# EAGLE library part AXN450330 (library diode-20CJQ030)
Matsushita P8 NARROW-PITCH CONNECTORS FOR PC BOARDS 50Pin Header NARROW-PITCH (0.8mm) CONNECTORS P8 SERIES FEATURES The product lineup consists of the low profile of: - 3 mm - 3.5 mm - 4 mm - 4.5 mm - 5 mm - 5.5 mm - 6 mm - 7 mm - 8 mm - 11.5 mm - 13 mm - 14 mm APPLICATIONS Small portable equipment, laptop computers, video equipment, radio communication, cellular telephones, etc. Please send any comments to: messi@users.sourceforge.net
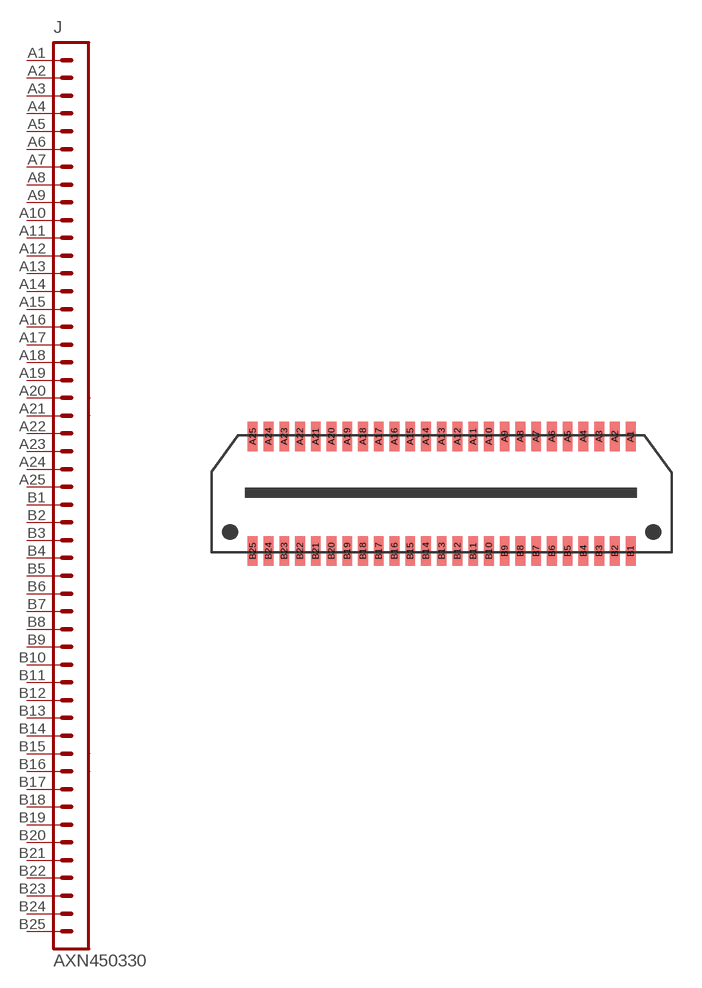
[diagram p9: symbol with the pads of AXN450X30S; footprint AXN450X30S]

Designator prefix J

## AXN450330  [AXN450X30S]
A1  1  pas
A2  2  pas
A3  3  pas
A4  4  pas
A5  5  pas
A6  6  pas
A7  7  pas
A8  8  pas
A9  9  pas
A10  10  pas
A11  11  pas
A12  12  pas
A13  13  pas
A14  14  pas
A15  15  pas
A16  16  pas
A17  17  pas
A18  18  pas
A19  19  pas
A20  20  pas
A21  21  pas
A22  22  pas
A23  23  pas
A24  24  pas
A25  25  pas
B1  26  pas
B2  27  pas
B3  28  pas
B4  29  pas
B5  30  pas
B6  31  pas
B7  32  pas
B8  33  pas
B9  34  pas
B10  35  pas
B11  36  pas
B12  37  pas
B13  38  pas
B14  39  pas
B15  40  pas
B16  41  pas
B17  42  pas
B18  43  pas
B19  44  pas
B20  45  pas
B21  46  pas
B22  47  pas
B23  48  pas
B24  49  pas
B25  50  pas

## Footprint AXN450X30S (pad centres in mm)
Matsushita NARROW-PITCH CONNECTORS FOR PC BOARDS 50Pin Header NARROW-PITCH (0.8mm) CONNECTORS P8 SERIES FEATURES The product lineup consists of the low profile of: - 3 mm - 3.5 mm - 4 mm - 4.5 mm - 5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
smd 0.5 x 1.5: A1 9.6,2.91; A2 8.8,2.91; A3 8,2.91; A4 7.2,2.91; A5 6.4,2.91; A6 5.6,2.91; A7 4.8,2.91; A8 4,2.91; A9 3.2,2.91; A10 2.4,2.91; A11 1.6,2.91; A12 0.8,2.91; A13 0,2.91; A14 -0.8,2.91; A15 -1.6,2.91; A16 -2.4,2.91; A17 -3.2,2.91; A18 -4,2.91; A19 -4.8,2.91; A20 -5.6,2.91; A21 -6.4,2.91; A22 -7.2,2.91; A23 -8,2.91; A24 -8.8,2.91; A25 -9.6,2.91; B1 9.6,-2.91; B2 8.8,-2.91; B3 8,-2.91; B4 7.2,-2.91; B5 6.4,-2.91; B6 5.6,-2.91; B7 4.8,-2.91; B8 4,-2.91; B9 3.2,-2.91; B10 2.4,-2.91; B11 1.6,-2.91; B12 0.8,-2.91; B13 0,-2.91; B14 -0.8,-2.91; B15 -1.6,-2.91; B16 -2.4,-2.91; B17 -3.2,-2.91; B18 -4,-2.91; B19 -4.8,-2.91; B20 -5.6,-2.91; B21 -6.4,-2.91; B22 -7.2,-2.91; B23 -8,-2.91; B24 -8.8,-2.91; B25 -9.6,-2.91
